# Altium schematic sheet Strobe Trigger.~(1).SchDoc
size B; Organization: Monterey Bay Aquarium Research Institute; Address1: 7700 Sandholdt Rd; Address2: Moss Landing, CA 95039-9644; CompanyName: MBARI
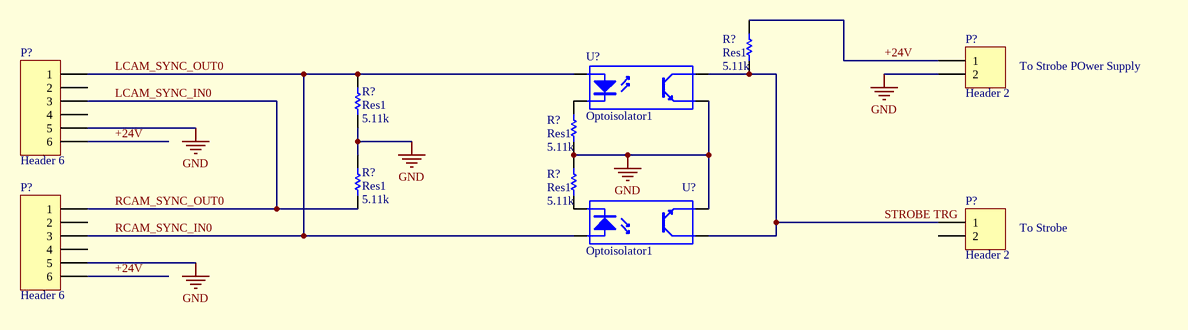
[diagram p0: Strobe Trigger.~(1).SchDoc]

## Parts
(Parts that share a designator on the sheet are numbered #1, #2 ... from top to bottom, then left to right.)
P?#1  Header 2  [HDR1X2]
P?#2  Header 6  [HDR1X6]
P?#3  Header 6  [HDR1X6]
P?#4  Header 2  [HDR1X2]
R?#1  Res1  value 5.11k  [AXIAL-0.3]
R?#2  Res1  value 5.11k  [AXIAL-0.3]
R?#3  Res1  value 5.11k  [AXIAL-0.3]
R?#4  Res1  value 5.11k  [AXIAL-0.3]
R?#5  Res1  value 5.11k  [AXIAL-0.3]
U?#1  Optoisolator1  [DIP-4]
U?#2  Optoisolator1  [DIP-4]

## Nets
GND: P?#1.2 P?#2.5 P?#3.5 R?#2.1 R?#3.1 R?#4.2 R?#5.2 U?#1.3(E) U?#2.3(E)
+24V: P?#1.1 P?#2.6 P?#3.6 R?#1.2
LCAM_SYNC_IN0: P?#2.3 P?#3.1 R?#4.1  [also labelled RCAM_SYNC_OUT0]
LCAM_SYNC_OUT0: P?#2.1 P?#3.3 R?#2.2 U?#1.1(A) U?#2.1(A)  [also labelled RCAM_SYNC_IN0]
STROBE TRG: P?#4.1 R?#1.1 U?#1.4(C) U?#2.4(C)
NetR?#3_2: R?#3.2 U?#1.2(K)
NetR?#5_1: R?#5.1 U?#2.2(K)

Not connected (* = marked no-connect by the designer): P?#2 2 4; P?#3 2 4; P?#4 2

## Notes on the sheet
- To Strobe POwer Supply
- To Strobe

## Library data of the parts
P?#1 P?#4 = Header 2: Header, 2-Pin
P?#2 P?#3 = Header 6: Header, 6-Pin
R?#1-R?#5 = Res1: Resistor
U?#1 U?#2 = Optoisolator1: 4-Pin Phototransistor Optocoupler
